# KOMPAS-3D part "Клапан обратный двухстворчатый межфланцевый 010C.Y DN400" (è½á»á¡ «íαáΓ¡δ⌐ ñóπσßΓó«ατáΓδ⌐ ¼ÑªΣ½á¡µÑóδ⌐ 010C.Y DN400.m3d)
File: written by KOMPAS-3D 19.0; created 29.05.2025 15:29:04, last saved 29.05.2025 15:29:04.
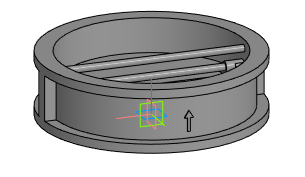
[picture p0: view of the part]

Document properties: Полное имя файла: E:\Dendor Работа Сачек\3D для проекитирвщиков\5.2 Тип 010C, 010C.Y Клапан обратный двухстворчатый межфланцевый\stp_Клапан обратный двухстворчатый межфланцевый 010C.Y\Клапан обратный двухстворчатый межфланцевый 010C.Y DN400.m3d

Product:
- Part/product: Клапан обратный двухстворчатый межфланцевый 010C.Y DN400

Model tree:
1. Операция без истории:1  (labels: Клапан обратный двухстворчатый межфланцевый 010C.Y DN400)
